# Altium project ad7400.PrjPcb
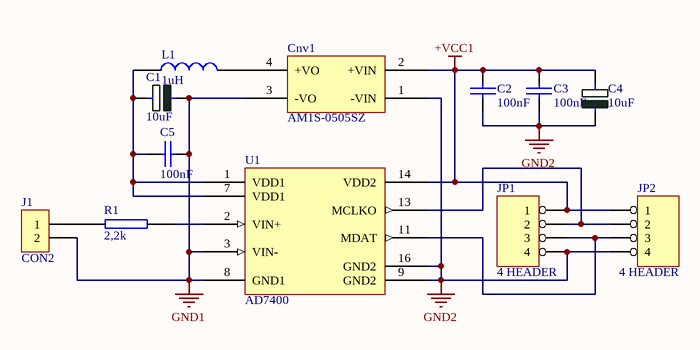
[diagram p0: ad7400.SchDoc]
1 sheet, 12 parts. Net scope: global (net labels, ports and power ports of the same name join across sheets).
Board file: ad7400.PcbDoc

## Sheet ad7400.SchDoc
size A4

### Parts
C1  10uF  [CE_SMD_W]
C2  100nF  [0805]
C3  100nF  [0805]
C4  10uF  [CE_SMD_W]
C5  100nF  [0805]
Cnv1  AM1S-0505SZ  [SIP4_AM1S]
J1  CON2  [ARK2]
JP1  4 HEADER  [GP4]
JP2  4 HEADER  [GP4]
L1  1uH  [0805]
R1  2,2k  [0805]
U1  AD7400  [SOL-16]

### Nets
+VCC1: C2.1 C3.1 C4.1(PLUS) Cnv1.2(+VIN) JP1.1 JP2.1 U1.14(VDD2)
GND1: C1.2(MINUS) C5.2 Cnv1.3(-VO) J1.2 U1.3(VIN-) U1.8(GND1)
GND2: C2.2 C3.2 C4.2(MINUS) Cnv1.1(-VIN) JP1.4 JP2.4 U1.9(GND2) U1.16(GND2)
NetC1_1: C1.1(PLUS) C5.1 L1.1 U1.1(VDD1) U1.7(VDD1)
NetCnv1_4: Cnv1.4(+VO) L1.2
NetJ1_1: J1.1 R1.1
NetJP1_2: JP1.2 JP2.2 U1.13(MCLKO)
NetJP1_3: JP1.3 JP2.3 U1.11(MDAT)
NetR1_2: R1.2 U1.2(VIN+)

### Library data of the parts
C1 C4 = CP: Capacitor
C2 C3 C5 = Cap: Capacitor
J1 = CON2: Connector
JP1 JP2 = HEADER 4: 4 Pin Header
L1 = INDUCTOR
R1 = RES2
